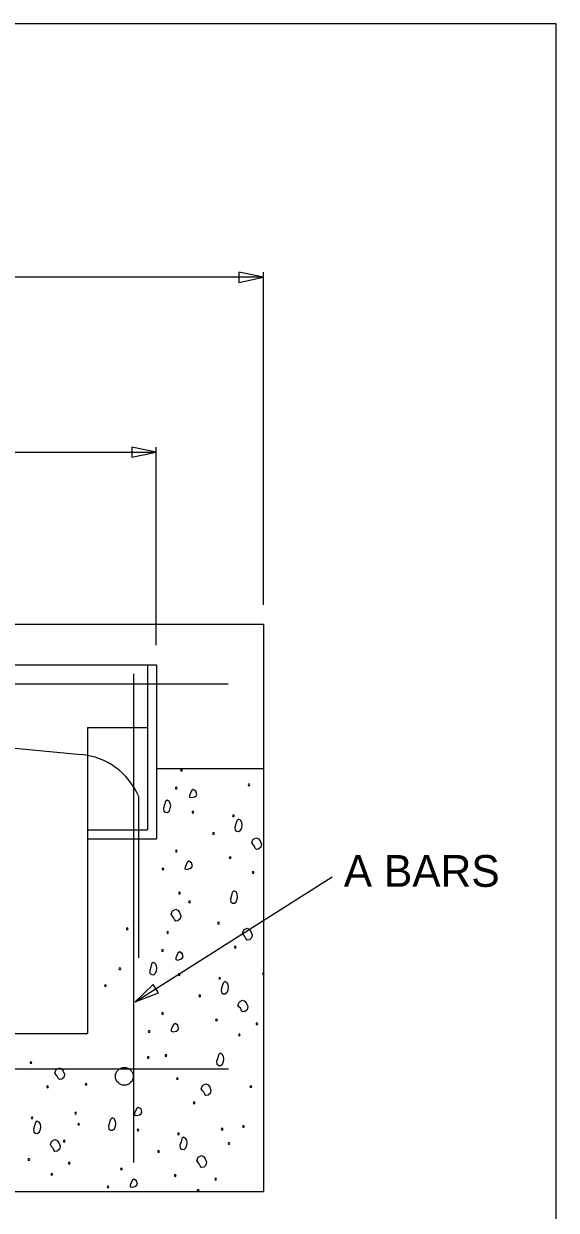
# Model space of a CAD drawing. Extents: x -439.1 to -407.9, y -458.1 to -436.2.
# Drawn here: x -410.37 to -407.86, y -443.28 to -437.68 of the extents above; entities that cross this region are included whole.
import ezdxf

# ---------------------------------------------------------------- set-up
doc = ezdxf.new("R2010")
doc.units = 0
doc.layers.add('Bridge-Named Boundary', color=7, linetype='Continuous')
doc.layers.add('Level 4', color=7, linetype='Continuous')

msp = doc.modelspace()

# ---------------------------------------------------------------- linework, layer by layer
at = {"layer": 'Bridge-Named Boundary'}
msp.add_lwpolyline([(-439.109, -458.0508), (-407.859, -458.0508), (-407.859, -437.6758), (-439.109, -437.6758)], close=True, dxfattribs=at)
at = {"layer": 'Level 4'}
for p, q in [((-409.241, -440.4195), (-409.241, -438.8489)), ((-409.241, -438.873), (-412.9232, -438.873)), ((-412.4593, -439.6987), (-409.7463, -439.6987)), ((-409.7463, -440.6103), (-409.7463, -439.6746)), ((-412.9234, -440.5115), (-409.241, -440.5115)), ((-409.241, -440.5115), (-409.241, -443.1901)), ((-412.4593, -440.7026), (-409.7461, -440.7026)), ((-409.7881, -440.7026), (-409.7881, -441.4817)), ((-409.7461, -440.7026), (-409.7461, -441.5237)), ((-409.8542, -440.7457), (-409.8542, -443.0525)), ((-412.8341, -440.7929), (-409.408, -440.7929)), ((-411.5741, -440.9882), (-410.101, -441.1258)), ((-410.0705, -440.9987), (-410.0705, -442.4435)), ((-410.0705, -440.9987), (-409.7881, -440.9987)), ((-409.7461, -441.1919), (-409.241, -441.1919)), ((-409.8301, -441.3221), (-409.8301, -442.0855)), ((-410.0705, -441.4817), (-409.7881, -441.4817)), ((-410.0705, -441.5237), (-409.7461, -441.5237)), ((-409.8464, -442.2939), (-408.9165, -441.7044)), ((-410.7482, -442.4435), (-410.0705, -442.4435)), ((-412.81, -442.6094), (-409.4059, -442.6094)), ((-412.9234, -443.1901), (-409.241, -443.1901))]:
    msp.add_line(p, q, dxfattribs=at)
for points in [[(-409.3571, -438.8972), (-409.241, -438.873), (-409.3571, -438.8489)], [(-409.8625, -439.7228), (-409.7463, -439.6987), (-409.8625, -439.6746)], [(-409.572, -441.291), (-409.5798, -441.2969), (-409.585, -441.3079), (-409.5897, -441.3191), (-409.5902, -441.3273), (-409.5807, -441.3297), (-409.5668, -441.326), (-409.559, -441.3213), (-409.5551, -441.3143), (-409.5594, -441.2984), (-409.572, -441.291)], [(-409.6958, -441.3411), (-409.7038, -441.3485), (-409.7075, -441.3632), (-409.7128, -441.3799), (-409.7114, -441.393), (-409.7032, -441.3986), (-409.6932, -441.3995), (-409.6848, -441.3921), (-409.6803, -441.38), (-409.6784, -441.3683), (-409.6803, -441.3567), (-409.6863, -441.3458), (-409.6958, -441.3411)], [(-409.3588, -441.4311), (-409.3667, -441.4385), (-409.3705, -441.4532), (-409.3758, -441.4699), (-409.3744, -441.483), (-409.3662, -441.4886), (-409.3562, -441.4895), (-409.3478, -441.4821), (-409.3432, -441.47), (-409.3414, -441.4583), (-409.3432, -441.4467), (-409.3492, -441.4358), (-409.3588, -441.4311)], [(-409.2963, -441.5422), (-409.2897, -441.5264), (-409.2742, -441.5188), (-409.2639, -441.5237), (-409.256, -441.5344), (-409.2503, -441.5496), (-409.2534, -441.5642), (-409.2635, -441.5731), (-409.2742, -441.5746), (-409.2796, -441.5676), (-409.2846, -441.5578), (-409.2916, -441.5502), (-409.2963, -441.5422)], [(-409.5931, -441.6299), (-409.6009, -441.6358), (-409.6061, -441.6468), (-409.6108, -441.658), (-409.6112, -441.6663), (-409.6018, -441.6686), (-409.5879, -441.665), (-409.5801, -441.6602), (-409.5762, -441.6533), (-409.5804, -441.6374), (-409.5931, -441.6299)], [(-409.3799, -441.77), (-409.3878, -441.7775), (-409.3915, -441.7921), (-409.3968, -441.8089), (-409.3954, -441.822), (-409.3872, -441.8276), (-409.3773, -441.8285), (-409.3688, -441.8211), (-409.3643, -441.809), (-409.3625, -441.7973), (-409.3643, -441.7856), (-409.3703, -441.7748), (-409.3799, -441.77)], [(-409.677, -441.8799), (-409.6704, -441.8642), (-409.655, -441.8566), (-409.6447, -441.8614), (-409.6368, -441.8721), (-409.6311, -441.8874), (-409.6342, -441.902), (-409.6442, -441.9108), (-409.655, -441.9124), (-409.6604, -441.9053), (-409.6653, -441.8955), (-409.6723, -441.8879), (-409.677, -441.8799)], [(-409.34, -441.9699), (-409.3334, -441.9542), (-409.3179, -441.9466), (-409.3076, -441.9514), (-409.2997, -441.9621), (-409.294, -441.9774), (-409.2971, -441.992), (-409.3072, -442.0008), (-409.3179, -442.0024), (-409.3234, -441.9953), (-409.3283, -441.9855), (-409.3353, -441.9779), (-409.34, -441.9699)], [(-409.6368, -442.0577), (-409.6446, -442.0636), (-409.6498, -442.0746), (-409.6545, -442.0858), (-409.655, -442.094), (-409.6455, -442.0964), (-409.6316, -442.0927), (-409.6238, -442.088), (-409.6199, -442.0811), (-409.6242, -442.0651), (-409.6368, -442.0577)], [(-409.7606, -442.1078), (-409.7686, -442.1152), (-409.7723, -442.1299), (-409.7776, -442.1466), (-409.7762, -442.1597), (-409.768, -442.1653), (-409.758, -442.1662), (-409.7496, -442.1588), (-409.745, -442.1467), (-409.7432, -442.135), (-409.745, -442.1234), (-409.7511, -442.1126), (-409.7606, -442.1078)], [(-409.7612, -442.2113), (-409.8464, -442.2939), (-409.7354, -442.2521)], [(-409.4236, -442.1978), (-409.4315, -442.2052), (-409.4353, -442.2199), (-409.4406, -442.2366), (-409.4392, -442.2497), (-409.431, -442.2553), (-409.421, -442.2562), (-409.4126, -442.2488), (-409.408, -442.2367), (-409.4062, -442.225), (-409.408, -442.2134), (-409.414, -442.2026), (-409.4236, -442.1978)], [(-409.361, -442.3089), (-409.3545, -442.2932), (-409.339, -442.2855), (-409.3287, -442.2904), (-409.3208, -442.3011), (-409.3151, -442.3164), (-409.3182, -442.331), (-409.3283, -442.3398), (-409.339, -442.3413), (-409.3444, -442.3343), (-409.3494, -442.3245), (-409.3564, -442.3169), (-409.361, -442.3089)], [(-409.6579, -442.3966), (-409.6657, -442.4025), (-409.6708, -442.4135), (-409.6756, -442.4247), (-409.676, -442.433), (-409.6666, -442.4353), (-409.6527, -442.4317), (-409.6449, -442.4269), (-409.641, -442.42), (-409.6452, -442.4041), (-409.6579, -442.3966)], [(-409.4447, -442.5368), (-409.4526, -442.5442), (-409.4563, -442.5588), (-409.4616, -442.5756), (-409.4602, -442.5887), (-409.452, -442.5943), (-409.4421, -442.5952), (-409.4336, -442.5878), (-409.4291, -442.5757), (-409.4272, -442.564), (-409.4291, -442.5523), (-409.4351, -442.5415), (-409.4447, -442.5368)], [(-410.2255, -442.6286), (-410.2189, -442.6129), (-410.2034, -442.6053), (-410.1931, -442.6101), (-410.1852, -442.6209), (-410.1795, -442.6361), (-410.1826, -442.6507), (-410.1927, -442.6596), (-410.2034, -442.6611), (-410.2089, -442.654), (-410.2138, -442.6442), (-410.2208, -442.6366), (-410.2255, -442.6286)], [(-409.5344, -442.7042), (-409.5278, -442.6885), (-409.5123, -442.6809), (-409.502, -442.6857), (-409.4941, -442.6965), (-409.4884, -442.7117), (-409.4915, -442.7263), (-409.5016, -442.7351), (-409.5123, -442.7367), (-409.5177, -442.7296), (-409.5227, -442.7198), (-409.5297, -442.7122), (-409.5344, -442.7042)], [(-409.955, -442.8421), (-409.9629, -442.8495), (-409.9667, -442.8642), (-409.972, -442.8809), (-409.9706, -442.894), (-409.9624, -442.8996), (-409.9524, -442.9005), (-409.944, -442.8931), (-409.9394, -442.881), (-409.9376, -442.8693), (-409.9394, -442.8577), (-409.9454, -442.8469), (-409.955, -442.8421)], [(-409.8312, -442.792), (-409.839, -442.7979), (-409.8442, -442.8089), (-409.8489, -442.8201), (-409.8493, -442.8283), (-409.8399, -442.8307), (-409.826, -442.827), (-409.8182, -442.8223), (-409.8143, -442.8154), (-409.8185, -442.7994), (-409.8312, -442.792)], [(-410.3091, -442.8565), (-410.317, -442.864), (-410.3208, -442.8786), (-410.3261, -442.8954), (-410.3247, -442.9084), (-410.3165, -442.914), (-410.3065, -442.9149), (-410.2981, -442.9075), (-410.2935, -442.8955), (-410.2917, -442.8837), (-410.2935, -442.8721), (-410.2995, -442.8613), (-410.3091, -442.8565)], [(-410.2465, -442.9676), (-410.24, -442.9519), (-410.2245, -442.9442), (-410.2142, -442.9491), (-410.2063, -442.9598), (-410.2006, -442.9751), (-410.2037, -442.9897), (-410.2138, -442.9985), (-410.2245, -443.0001), (-410.2299, -442.993), (-410.2349, -442.9832), (-410.2419, -442.9756), (-410.2465, -442.9676)], [(-409.618, -442.9321), (-409.6259, -442.9395), (-409.6296, -442.9542), (-409.6349, -442.9709), (-409.6335, -442.984), (-409.6253, -442.9896), (-409.6154, -442.9905), (-409.6069, -442.9831), (-409.6024, -442.9711), (-409.6006, -442.9593), (-409.6024, -442.9477), (-409.6084, -442.9369), (-409.618, -442.9321)], [(-409.5554, -443.0432), (-409.5488, -443.0275), (-409.5334, -443.0198), (-409.5231, -443.0247), (-409.5152, -443.0354), (-409.5095, -443.0507), (-409.5126, -443.0653), (-409.5226, -443.0741), (-409.5334, -443.0756), (-409.5388, -443.0686), (-409.5437, -443.0588), (-409.5507, -443.0512), (-409.5554, -443.0432)], [(-409.8522, -443.131), (-409.86, -443.1368), (-409.8652, -443.1478), (-409.87, -443.1591), (-409.8704, -443.1673), (-409.8609, -443.1696), (-409.847, -443.166), (-409.8393, -443.1612), (-409.8354, -443.1543), (-409.8396, -443.1384), (-409.8522, -443.131)]]:
    msp.add_lwpolyline(points, close=True, dxfattribs=at)
msp.add_circle((-409.8972, -442.6457), 0.042, dxfattribs=at)
for centre, radius, start, end in [((-410.1309, -441.4525), 0.3277, 23.4904, 84.6809), ((-409.6278, -441.2), 0.00416, 0, 180), ((-409.6278, -441.2), 0.00416, 180, 0), ((-409.309, -441.2696), 0.00416, 0, 180), ((-409.309, -441.2696), 0.00416, 180, 0), ((-409.6524, -441.2846), 0.00416, 0, 180), ((-409.6524, -441.2846), 0.00416, 180, 0), ((-409.5735, -441.3986), 0.00416, 0, 180), ((-409.5735, -441.3986), 0.00416, 180, 0), ((-409.3827, -441.4161), 0.00416, 0, 180), ((-409.3827, -441.4161), 0.00416, 180, 0), ((-409.4766, -441.499), 0.00416, 0, 180), ((-409.4766, -441.499), 0.00416, 180, 0), ((-409.652, -441.5822), 0.00416, 0, 180), ((-409.652, -441.5822), 0.00416, 180, 0), ((-409.3977, -441.6131), 0.00416, 0, 180), ((-409.3977, -441.6131), 0.00416, 180, 0), ((-409.7153, -441.6667), 0.00416, 0, 180), ((-409.7153, -441.6667), 0.00416, 180, 0), ((-409.2896, -441.6829), 0.00416, 0, 180), ((-409.2896, -441.6829), 0.00416, 180, 0), ((-409.6364, -441.7808), 0.00416, 0, 180), ((-409.6364, -441.7808), 0.00416, 180, 0), ((-409.5899, -441.8218), 0.00416, 0, 180), ((-409.5899, -441.8218), 0.00416, 180, 0), ((-409.8834, -441.9492), 0.00416, 0, 180), ((-409.8834, -441.9492), 0.00416, 180, 0), ((-409.4527, -441.9223), 0.00416, 0, 180), ((-409.4527, -441.9223), 0.00416, 180, 0), ((-409.6926, -441.9667), 0.00416, 0, 180), ((-409.6926, -441.9667), 0.00416, 180, 0), ((-409.7172, -442.0513), 0.00416, 0, 180), ((-409.7172, -442.0513), 0.00416, 180, 0), ((-409.3738, -442.0363), 0.00416, 0, 180), ((-409.3738, -442.0363), 0.00416, 180, 0), ((-409.9184, -442.1377), 0.00416, 0, 180), ((-409.9184, -442.1377), 0.00416, 180, 0), ((-409.6383, -442.1653), 0.00416, 0, 180), ((-409.6383, -442.1653), 0.00416, 180, 0), ((-409.2415, -442.1609), 0.00416, 0, 180), ((-409.2415, -442.1609), 0.00416, 180, 0), ((-409.9865, -442.2174), 0.00416, 0, 180), ((-409.9865, -442.2174), 0.00416, 180, 0), ((-409.4475, -442.1828), 0.00416, 0, 180), ((-409.4475, -442.1828), 0.00416, 180, 0), ((-409.5414, -442.2657), 0.00416, 0, 180), ((-409.5414, -442.2657), 0.00416, 180, 0), ((-409.7168, -442.3489), 0.00416, 0, 180), ((-409.7168, -442.3489), 0.00416, 180, 0), ((-409.4625, -442.3798), 0.00416, 0, 180), ((-409.4625, -442.3798), 0.00416, 180, 0), ((-409.2717, -442.3973), 0.00416, 0, 180), ((-409.2717, -442.3973), 0.00416, 180, 0), ((-409.7801, -442.4334), 0.00416, 0, 180), ((-409.7801, -442.4334), 0.00416, 180, 0), ((-409.3544, -442.4496), 0.00416, 0, 180), ((-409.3544, -442.4496), 0.00416, 180, 0), ((-409.7843, -442.5561), 0.00416, 0, 180), ((-409.7843, -442.5561), 0.00416, 180, 0), ((-409.7012, -442.5475), 0.00416, 0, 180), ((-409.7012, -442.5475), 0.00416, 180, 0), ((-410.3382, -442.581), 0.00416, 0, 180), ((-410.3382, -442.581), 0.00416, 180, 0), ((-409.6471, -442.6566), 0.00416, 0, 180), ((-409.6471, -442.6566), 0.00416, 180, 0), ((-410.2593, -442.695), 0.00416, 0, 180), ((-410.2593, -442.695), 0.00416, 180, 0), ((-410.0778, -442.6835), 0.00416, 0, 180), ((-410.0778, -442.6835), 0.00416, 180, 0), ((-409.3002, -442.6943), 0.00416, 0, 180), ((-409.3002, -442.6943), 0.00416, 180, 0), ((-409.5682, -442.7706), 0.00416, 0, 180), ((-409.5682, -442.7706), 0.00416, 180, 0), ((-410.333, -442.8416), 0.00416, 0, 180), ((-410.333, -442.8416), 0.00416, 180, 0), ((-410.127, -442.8196), 0.00416, 0, 180), ((-410.127, -442.8196), 0.00416, 180, 0), ((-410.1127, -442.872), 0.00416, 0, 180), ((-410.1127, -442.872), 0.00416, 180, 0), ((-409.8326, -442.8996), 0.00416, 0, 180), ((-409.8326, -442.8996), 0.00416, 180, 0), ((-409.4359, -442.8952), 0.00416, 0, 180), ((-409.4359, -442.8952), 0.00416, 180, 0), ((-409.3352, -442.8828), 0.00416, 0, 180), ((-409.3352, -442.8828), 0.00416, 180, 0), ((-410.1809, -442.9517), 0.00416, 0, 180), ((-410.1809, -442.9517), 0.00416, 180, 0), ((-409.6419, -442.9171), 0.00416, 0, 180), ((-409.6419, -442.9171), 0.00416, 180, 0), ((-409.4034, -442.9625), 0.00416, 0, 180), ((-409.7358, -443.0001), 0.00416, 0, 180), ((-409.7358, -443.0001), 0.00416, 180, 0), ((-409.4034, -442.9625), 0.00416, 180, 0), ((-410.348, -443.0385), 0.00416, 0, 180), ((-410.348, -443.0385), 0.00416, 180, 0), ((-410.1572, -443.056), 0.00416, 0, 180), ((-410.1572, -443.056), 0.00416, 180, 0), ((-410.2399, -443.1083), 0.00416, 0, 180), ((-410.2399, -443.1083), 0.00416, 180, 0), ((-409.9112, -443.0832), 0.00416, 0, 180), ((-409.9112, -443.0832), 0.00416, 180, 0), ((-409.6569, -443.1141), 0.00416, 0, 180), ((-409.6569, -443.1141), 0.00416, 180, 0), ((-409.9745, -443.1678), 0.00416, 0, 180), ((-409.9745, -443.1678), 0.00416, 180, 0), ((-409.5487, -443.1839), 0.00416, 0, 180), ((-409.4661, -443.1316), 0.00416, 0, 180), ((-409.4661, -443.1316), 0.00416, 180, 0), ((-409.5487, -443.1839), 0.00416, 180, 0)]:
    msp.add_arc(centre, radius, start, end, dxfattribs=at)

# ---------------------------------------------------------------- texts
msp.add_text('A BARS', height=0.15, dxfattribs=at).set_placement((-408.8618, -441.7508))

doc.saveas('drawing.dxf')
